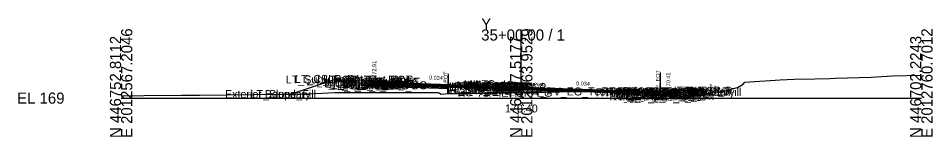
# Model space of a CAD drawing. Extents: x -26 to 3203, y -10 to 9532.
# Drawn here: x 1974.3 to 2202.8, y 8990.3 to 9020 of the extents above; entities that cross this region are included whole.
import ezdxf

# ---------------------------------------------------------------- set-up
doc = ezdxf.new("R2010")
doc.units = 0
for name, color, linetype in [('Default', 7, 'Continuous'), ('Exist CMT Pavement', 7, 'Continuous'), ('Exist Cross Section Cell', 7, 'Continuous'), ('Exist XS Center Line Elevation Label', 7, 'Continuous'), ('Exist XS Ground Line', 7, 'Continuous'), ('Prop CMT Conc Surface', 7, 'Continuous'), ('Prop CMT Concrete Structures', 7, 'Continuous'), ('Prop CMT Pvmt Course 1', 7, 'Continuous'), ('Prop CMT Pvmt Course 1 CG', 7, 'Continuous'), ('Prop CMT Pvmt Course 1 Wedge', 7, 'Continuous'), ('Prop CMT Pvmt Course 2', 7, 'Continuous'), ('Prop CMT Pvmt Course 2 Wedge', 7, 'Continuous'), ('Prop CMT Pvmt Course 3', 7, 'Continuous'), ('Prop CMT Pvmt Course 3 Wedge', 7, 'Continuous'), ('Prop CMT Pvmt Surface', 7, 'Continuous'), ('Prop CMT Pvmt Wedge Surface 1', 7, 'Continuous'), ('Prop CMT Pvmt Wedge Surface 2', 7, 'Continuous'), ('Prop CMT Pvmt Wedge Surface 3', 7, 'Continuous'), ('Prop CMT Slope Grass', 7, 'Continuous'), ('Prop CMT Subgrade Earthwork', 7, 'Continuous'), ('Prop XS Hydro Elevations', 7, 'Continuous'), ('Prop XS Label Text', 7, 'Continuous'), ('Prop XS SE Text', 7, 'Continuous'), ('Prop XS Side Slope Text', 7, 'Continuous'), ('Scratch_Level_0', 7, 'Continuous')]:
    doc.layers.add(name, color=color, linetype=linetype)

msp = doc.modelspace()

# ---------------------------------------------------------------- linework, layer by layer
at = {"layer": 'Exist CMT Pavement'}
for points in [[(2114.87, 9001.67), (2096, 9001.34)], [(2132.75, 9001.5), (2114.87, 9001.67)]]:
    msp.add_lwpolyline(points, dxfattribs=at)
at = {"layer": 'Exist Cross Section Cell'}
for p, q in [((2100, 9000), (2100, 9017.23)), ((2000, 9000), (2100, 9000)), ((2100, 9000), (2200, 9000))]:
    msp.add_line(p, q, dxfattribs=at)
at = {"layer": 'Exist XS Ground Line'}
msp.add_lwpolyline([(2000, 9000.58), (2005.69, 9000.63), (2015.07, 9000.72), (2019.58, 9000.75), (2040.24, 9001), (2041.62, 9001.01), (2045.25, 9001.08), (2046.89, 9001.09), (2053.45, 9001.4), (2054.76, 9001.42), (2063.44, 9001.43), (2077.33, 9001.4), (2079.21, 9001.42), (2079.58, 9001.21), (2080.02, 9000.95), (2080.98, 9001.05), (2081.74, 9001.12), (2082.58, 9001.15), (2083.46, 9001.17), (2085.1, 9001.2), (2086.1, 9001.21), (2087.68, 9001.23), (2090.25, 9001.27), (2092.14, 9001.3), (2092.44, 9001.3), (2092.82, 9001.31), (2093.83, 9001.32), (2095.4, 9001.34), (2096.31, 9001.35), (2097.98, 9001.37), (2098.36, 9001.38), (2100, 9001.4), (2100.55, 9001.41), (2101.04, 9001.41), (2103.12, 9001.44), (2103.97, 9001.47), (2105.72, 9001.52), (2106.54, 9001.54), (2108.3, 9001.58), (2109.59, 9001.6), (2110.85, 9001.62), (2111.97, 9001.64), (2113.43, 9001.66), (2113.97, 9001.66), (2116.11, 9001.69), (2118.85, 9001.7), (2119.53, 9001.7), (2120.93, 9001.7), (2121.28, 9001.7), (2121.87, 9001.69), (2124.12, 9001.65), (2125.6, 9001.63), (2126.45, 9001.61), (2127.07, 9001.6), (2129.13, 9001.57), (2129.48, 9001.56), (2131.61, 9001.52), (2132.36, 9001.51), (2134.18, 9001.47), (2134.76, 9001.46), (2135.84, 9001.45), (2136.75, 9001.43), (2139.37, 9001.39), (2141.38, 9001.35), (2141.9, 9001.34), (2142.76, 9001.33), (2144.45, 9001.29), (2144.87, 9001.28), (2145.3, 9001.26), (2145.88, 9001.22), (2147.07, 9001.12), (2147.85, 9001.59), (2149.84, 9001.61), (2150.21, 9001.62), (2150.85, 9001.79), (2154.09, 9002.65), (2155.46, 9003.51), (2155.92, 9003.98), (2164.74, 9004.55), (2168.18, 9004.74), (2173.38, 9004.86), (2177.15, 9004.96), (2178.49, 9004.99), (2187.49, 9005.26), (2192.76, 9005.59), (2200, 9005.74)], dxfattribs=at)
at = {"layer": 'Prop CMT Conc Surface'}
for points in [[(2058.75, 9004.5), (2053.75, 9004.6)], [(2063.25, 9003.91), (2063.25, 9004.41), (2062.75, 9004.41)], [(2065.25, 9003.93), (2063.25, 9003.91)], [(2136.75, 9001.41), (2136.75, 9001.91), (2137.25, 9001.91)], [(2141.25, 9002), (2146.25, 9002.1)], [(2134.75, 9001.55), (2136.75, 9001.41)]]:
    msp.add_lwpolyline(points, dxfattribs=at)
at = {"layer": 'Prop CMT Concrete Structures'}
for points in [[(2053.75, 9004.27), (2053.75, 9004.6)], [(2053.75, 9004.6), (2058.75, 9004.5)], [(2058.75, 9004.17), (2053.75, 9004.27)], [(2058.75, 9004.5), (2058.75, 9004.17)], [(2065.25, 9003.93), (2063.25, 9003.91), (2063.25, 9004.41), (2062.75, 9004.41)], [(2062.75, 9004.41), (2062.75, 9003.43), (2065.25, 9003.34)], [(2065.25, 9003.34), (2065.25, 9003.93)], [(2096, 9002.88), (2095.99, 9003.04), (2095.24, 9003.29), (2094, 9003.45), (2092.76, 9003.43), (2092.01, 9003.18), (2092, 9003.01)], [(2092, 9003.01), (2096, 9002.88)], [(2134.75, 9001.55), (2136.75, 9001.41), (2136.75, 9001.91), (2137.25, 9001.91)], [(2137.25, 9001.91), (2137.25, 9000.89), (2134.75, 9000.97)], [(2146.25, 9002.1), (2141.25, 9002)], [(2141.25, 9002), (2141.25, 9001.66)], [(2146.25, 9001.76), (2146.25, 9002.1)], [(2134.75, 9000.97), (2134.75, 9001.55)], [(2141.25, 9001.66), (2146.25, 9001.76)]]:
    msp.add_lwpolyline(points, dxfattribs=at)
at = {"layer": 'Prop CMT Pvmt Course 1'}
for points in [[(2092, 9003.01), (2065.25, 9003.93)], [(2065.25, 9003.93), (2065.25, 9003.68)], [(2065.25, 9003.68), (2092, 9002.76)], [(2092, 9003.01), (2096, 9002.88)], [(2092, 9002.76), (2092, 9003.01)], [(2092, 9002.76), (2092, 9003.01)], [(2096, 9002.63), (2092, 9002.76)], [(2096, 9002.88), (2134.75, 9001.55)], [(2096, 9002.63), (2096, 9002.88)], [(2096, 9002.88), (2096, 9002.63)], [(2132.75, 9001.5), (2096, 9002.75)], [(2096, 9002.75), (2096, 9002.63), (2096, 9002.63)], [(2132.75, 9001.37), (2132.75, 9001.5)], [(2134.75, 9001.3), (2133.75, 9001.34)], [(2134.75, 9001.55), (2134.75, 9001.3)]]:
    msp.add_lwpolyline(points, dxfattribs=at)
msp.add_lwpolyline([(2092, 9002.76), (2092, 9002.89), (2092, 9002.89), (2092, 9002.76)], close=True, dxfattribs=at)
at = {"layer": 'Prop CMT Pvmt Course 1 CG'}
for points in [[(2065.25, 9003.34), (2062.25, 9003.45), (2061.93, 9003.12)], [(2061.93, 9003.12), (2065.25, 9003.01)], [(2065.25, 9003.01), (2065.25, 9003.34)], [(2134.75, 9000.97), (2137.75, 9000.87), (2138.1, 9000.52)], [(2134.75, 9000.64), (2134.75, 9000.97)], [(2138.1, 9000.52), (2134.75, 9000.64)]]:
    msp.add_lwpolyline(points, dxfattribs=at)
at = {"layer": 'Prop CMT Pvmt Course 1 Wedge'}
for points in [[(2096, 9002.75), (2096.31, 9002.74), (2097.98, 9002.68), (2098.36, 9002.67), (2099.77, 9002.62), (2100.39, 9002.6), (2100.55, 9002.6), (2101.04, 9002.58), (2103.08, 9002.51), (2103.12, 9002.51), (2103.97, 9002.48), (2105.72, 9002.42), (2106.54, 9002.39), (2108.3, 9002.33), (2109.59, 9002.29), (2110.85, 9002.25), (2111.97, 9002.21), (2113.43, 9002.16), (2113.43, 9002.16), (2113.97, 9002.14), (2116.11, 9002.07), (2118.4, 9001.99), (2118.68, 9001.98), (2118.85, 9001.97), (2119.53, 9001.95), (2120.93, 9001.9), (2121.28, 9001.89), (2121.87, 9001.87), (2123.86, 9001.8), (2123.92, 9001.8), (2124.12, 9001.79), (2125.6, 9001.74), (2126.45, 9001.71), (2127.07, 9001.69), (2129.04, 9001.62), (2129.13, 9001.62), (2129.48, 9001.61), (2131.61, 9001.54), (2132.36, 9001.51), (2132.66, 9001.5)], [(2096, 9002.63), (2096, 9002.75)], [(2132.66, 9001.5), (2132.36, 9001.51), (2131.61, 9001.52), (2129.48, 9001.56), (2129.13, 9001.57), (2129.04, 9001.57), (2127.07, 9001.6), (2126.45, 9001.61), (2125.6, 9001.63), (2125.03, 9001.64), (2124.12, 9001.67), (2123.92, 9001.67), (2123.86, 9001.68), (2121.87, 9001.74), (2121.28, 9001.76), (2120.93, 9001.78), (2119.53, 9001.82), (2118.85, 9001.85), (2118.68, 9001.85), (2118.4, 9001.86), (2116.11, 9001.94), (2113.97, 9002.01), (2113.43, 9002.03), (2113.43, 9002.03), (2111.97, 9002.08), (2110.85, 9002.12), (2109.59, 9002.16), (2108.3, 9002.21), (2106.54, 9002.27), (2105.72, 9002.3), (2103.97, 9002.35), (2103.12, 9002.38), (2103.08, 9002.39), (2101.04, 9002.46), (2100.55, 9002.47), (2100.39, 9002.48), (2099.77, 9002.5), (2098.36, 9002.55), (2097.98, 9002.56), (2096.31, 9002.62), (2096, 9002.63)]]:
    msp.add_lwpolyline(points, dxfattribs=at)
at = {"layer": 'Prop CMT Pvmt Course 2'}
for points in [[(2092, 9002.76), (2065.25, 9003.68)], [(2065.25, 9003.68), (2065.25, 9003.34)], [(2065.25, 9003.34), (2092, 9002.43)], [(2092, 9002.76), (2096, 9002.63)], [(2092, 9002.43), (2092, 9002.76)], [(2092, 9002.43), (2092, 9002.76)], [(2096, 9002.29), (2092, 9002.43)], [(2096, 9002.63), (2096, 9002.29)], [(2132.75, 9001.04), (2132.75, 9001.37)], [(2132.75, 9001.37), (2134.75, 9001.3)], [(2134.75, 9000.97), (2132.75, 9001.04)], [(2134.75, 9001.3), (2134.75, 9000.97)]]:
    msp.add_lwpolyline(points, dxfattribs=at)
at = {"layer": 'Prop CMT Pvmt Course 2 Wedge'}
for points in [[(2096, 9002.63), (2096.31, 9002.62), (2097.98, 9002.56), (2098.36, 9002.55), (2099.77, 9002.5), (2100.39, 9002.48), (2100.55, 9002.47), (2101.04, 9002.46), (2103.08, 9002.39), (2103.12, 9002.38), (2103.97, 9002.35), (2105.72, 9002.3), (2106.54, 9002.27), (2108.3, 9002.21), (2109.59, 9002.16), (2110.85, 9002.12), (2111.97, 9002.08), (2113.43, 9002.03), (2113.43, 9002.03), (2113.97, 9002.01), (2116.11, 9001.94), (2118.4, 9001.86), (2118.68, 9001.85), (2118.85, 9001.85), (2119.53, 9001.82), (2120.93, 9001.78), (2121.28, 9001.76), (2121.87, 9001.74), (2123.86, 9001.68), (2123.92, 9001.67), (2124.12, 9001.67), (2125.03, 9001.64)], [(2096, 9002.29), (2096, 9002.63)], [(2125.03, 9001.64), (2124.12, 9001.65), (2123.92, 9001.65), (2123.86, 9001.66), (2121.87, 9001.69), (2121.28, 9001.7), (2120.93, 9001.7), (2119.53, 9001.7), (2118.85, 9001.7), (2118.68, 9001.7), (2118.4, 9001.7), (2116.11, 9001.69), (2114.34, 9001.67), (2113.97, 9001.68), (2113.43, 9001.7), (2113.43, 9001.7), (2111.97, 9001.75), (2110.85, 9001.79), (2109.59, 9001.83), (2108.3, 9001.87), (2106.54, 9001.93), (2105.72, 9001.96), (2103.97, 9002.02), (2103.12, 9002.05), (2103.08, 9002.05), (2101.04, 9002.12), (2100.55, 9002.14), (2100.39, 9002.14), (2099.77, 9002.16), (2098.36, 9002.21), (2097.98, 9002.23), (2096.31, 9002.28), (2096, 9002.29)]]:
    msp.add_lwpolyline(points, dxfattribs=at)
at = {"layer": 'Prop CMT Pvmt Course 3'}
for points in [[(2092, 9002.43), (2065.25, 9003.34)], [(2065.25, 9003.34), (2065.25, 9003.01)], [(2065.25, 9003.01), (2081.74, 9002.45)], [(2092, 9002.43), (2096, 9002.29)], [(2132.75, 9001.04), (2134.75, 9000.97)], [(2132.75, 9000.71), (2132.75, 9001.04)], [(2134.75, 9000.64), (2132.75, 9000.71)], [(2134.75, 9000.97), (2134.75, 9000.64)]]:
    msp.add_lwpolyline(points, dxfattribs=at)
at = {"layer": 'Prop CMT Pvmt Course 3 Wedge'}
for points in [[(2096, 9002.29), (2096.31, 9002.28), (2097.98, 9002.23), (2098.36, 9002.21), (2099.77, 9002.16), (2100.39, 9002.14), (2100.55, 9002.14), (2101.04, 9002.12), (2103.08, 9002.05), (2103.12, 9002.05), (2103.97, 9002.02), (2105.72, 9001.96), (2106.54, 9001.93), (2108.3, 9001.87), (2109.59, 9001.83), (2110.85, 9001.79), (2111.97, 9001.75), (2113.43, 9001.7), (2113.43, 9001.7), (2113.97, 9001.68), (2114.34, 9001.67)], [(2114.34, 9001.67), (2113.97, 9001.66), (2113.43, 9001.66), (2113.43, 9001.66), (2111.97, 9001.64), (2110.85, 9001.62), (2109.59, 9001.6), (2108.3, 9001.58), (2106.54, 9001.54), (2105.72, 9001.52), (2103.97, 9001.47), (2103.12, 9001.44), (2103.08, 9001.44), (2101.04, 9001.41), (2100.55, 9001.41), (2100.39, 9001.4), (2099.77, 9001.4), (2098.36, 9001.38), (2097.98, 9001.37), (2096.31, 9001.35), (2096, 9001.34)]]:
    msp.add_lwpolyline(points, dxfattribs=at)
at = {"layer": 'Prop CMT Pvmt Surface'}
for points in [[(2092, 9003.01), (2065.25, 9003.93)], [(2092, 9003.01), (2096, 9002.88)], [(2096, 9002.88), (2134.75, 9001.55)]]:
    msp.add_lwpolyline(points, dxfattribs=at)
at = {"layer": 'Prop CMT Pvmt Wedge Surface 1'}
for points in [[(2096, 9002.88), (2096, 9002.63), (2096, 9002.63), (2096, 9002.75)], [(2096, 9002.75), (2132.75, 9001.5)], [(2132.75, 9001.5), (2132.75, 9001.37)], [(2134.75, 9001.3), (2134.75, 9001.55)]]:
    msp.add_lwpolyline(points, dxfattribs=at)
at = {"layer": 'Prop CMT Pvmt Wedge Surface 2'}
for points in [[(2096, 9002.88), (2096, 9002.63)], [(2096, 9002.63), (2132.75, 9001.37)], [(2134.75, 9001.3), (2134.75, 9001.55)]]:
    msp.add_lwpolyline(points, dxfattribs=at)
at = {"layer": 'Prop CMT Pvmt Wedge Surface 3'}
for points in [[(2096, 9002.88), (2096, 9002.29)], [(2096, 9002.29), (2132.75, 9001.04)], [(2134.75, 9000.97), (2134.75, 9001.55)]]:
    msp.add_lwpolyline(points, dxfattribs=at)
at = {"layer": 'Prop CMT Slope Grass'}
for points in [[(2062.75, 9004.41), (2053.25, 9004.6), (2042.52, 9001.03)], [(2137.25, 9001.91), (2146.25, 9002.09)], [(2146.25, 9002.09), (2146.75, 9002.1), (2148.27, 9001.59)]]:
    msp.add_lwpolyline(points, dxfattribs=at)
at = {"layer": 'Prop CMT Subgrade Earthwork'}
for p, q in [((2081.74, 9002.45), (2081.74, 9001.12)), ((2132.75, 9001.5), (2132.75, 9000.71))]:
    msp.add_line(p, q, dxfattribs=at)
for points in [[(2065.25, 9003.01), (2061.93, 9003.12), (2060.59, 9004.46)], [(2081.74, 9002.45), (2065.25, 9003.01)], [(2134.75, 9000.64), (2138.1, 9000.52), (2139.52, 9001.95)], [(2132.75, 9000.71), (2134.75, 9000.64)]]:
    msp.add_lwpolyline(points, dxfattribs=at)
at = {"layer": 'Prop XS Label Text'}
for p, q in [((2081.74, 9006.12), (2081.74, 9001.12)), ((2134.76, 9006.46), (2134.76, 9001.46))]:
    msp.add_line(p, q, dxfattribs=at)

# ---------------------------------------------------------------- texts
at = {"layer": 'Default'}
msp.add_text('-', height=0.0001, dxfattribs=at).set_placement((2000, 9000))
at = {"layer": 'Exist Cross Section Cell'}
for s, p in [('Y', (2090, 9017.23)), ('35+00.00 / 1', (2090, 9014.43)), ('EL 169', (1974, 8998.6))]:
    msp.add_text(s, height=2.8, dxfattribs=at).set_placement(p)
for s, p in [('E 2012567.2046', (2002.8, 8990)), ('E 2012663.9529', (2102.8, 8990)), ('E 2012760.7012', (2202.8, 8990)), ('N 446752.8112', (2000, 8990)), ('N 446727.5177', (2100, 8990)), ('N 446702.2243', (2200, 8990))]:
    msp.add_text(s, height=2.8, rotation=90, dxfattribs=at).set_placement(p)
at = {"layer": 'Exist XS Center Line Elevation Label'}
msp.add_text('170.40', height=2, dxfattribs=at).set_placement((2095.95, 8996.4))
at = {"layer": 'Prop XS Hydro Elevations'}
for s, p in [('172.91', (2063.75, 9005.13)), ('170.41', (2137.25, 9002.19))]:
    msp.add_text(s, height=1, rotation=90, dxfattribs=at).set_placement(p)
at = {"layer": 'Prop XS Label Text'}
for p in [(2081.64, 9002.15), (2134.66, 9002.49)]:
    msp.add_text('E. EOT', height=1, rotation=90, dxfattribs=at).set_placement(p)
at = {"layer": 'Prop XS SE Text'}
for p in [(2076.94, 9004.66), (2113.69, 9003.19)]:
    msp.add_text('0.034', height=1, rotation=357.7094, dxfattribs=at).set_placement(p)
at = {"layer": 'Prop XS Side Slope Text'}
for rotation, p in [(18.4349, (2046.55, 9003.38)), (341.5651, (2146.75, 9002.67))]:
    msp.add_text('3:1', height=1, rotation=rotation, dxfattribs=at).set_placement(p)
at = {"layer": 'Scratch_Level_0'}
for s, p in [('LT_Sub_Trench_Out_DLT', (2041.17, 9003.67)), ('LT_CSLP_Pnt', (2043.42, 9003.82)), ('LT_CG1_Shelf_Out', (2048.8, 9002.67)), ('LT_CG_Top_Face', (2050.51, 9003.63)), ('LT_CG_Top_BOC', (2051.03, 9003.63)), ('LT_CG_Bot_BOC', (2051.06, 9002.65)), ('LT_CG_Top_Gut', (2051.49, 9003.13)), ('LT_Sub_OEOP', (2052.04, 9002.35)), ('LT_Sub_OEOT_CG', (2052.62, 9002.21)), ('LT_CG_Bot_IE', (2055.16, 9002.55)), ('LT_Sub_OEOT', (2055.33, 9002.21)), ('LT_PV2_OEOT', (2055.42, 9002.88)), ('LT_PV3_OEOT', (2055.42, 9002.55)), ('LT_PV1_OEOT', (2055.99, 9003.13)), ('MI_Face In', (2083.9, 9002.23)), ('MI_Top In', (2085.61, 9002.48)), ('MI_Top Out', (2086.47, 9002.32)), ('MI_Crown', (2087.07, 9002.5)), ('Exterior Boundary', (2025.97, 9000.01)), ('LT_Slope_Fill', (2032.35, 9000.01)), ('LT_Sub_OEEOP', (2081.21, 9001.14)), ('LT_PV2_OEEOP', (2081.31, 9001.81)), ('LT_PV3_OEEOP', (2081.31, 9001.48)), ('LT_PV1_OEEOP', (2081.87, 9001.94)), ('LT_PV2_IEEOP', (2081.95, 9001.81)), ('LT_PV1_IEEOP', (2082.52, 9001.94)), ('LT_PV2_PGL1', (2082.88, 9001.81)), ('LT_PV3_PGL1', (2082.88, 9001.48)), ('LT_PV2_PGL', (2083.21, 9001.81)), ('LT_PV4_PGL', (2083.21, 9001.14)), ('LT_PV1_PGL', (2083.78, 9002.06)), ('RT_PV_IEEOP_EG', (2084.14, 9000.34)), ('RT_PV2_IEEOP', (2085.91, 9001.65)), ('RT_PV3_IEEOP', (2085.91, 9001.32)), ('MI_Face Out', (2086.26, 9002.07)), ('RT_PV1_IEEOP', (2086.47, 9001.78)), ('RT_PV2_PGL1', (2086.83, 9001.65)), ('RT_PV3_PGL1', (2086.83, 9001.32)), ('RT_PV2_PGL', (2087.17, 9001.65)), ('RT_PV3_PGL', (2087.17, 9001.32)), ('RT_PV4_PGL', (2087.17, 9000.98)), ('MI_Bot Out', (2087.26, 9001.9)), ('RT_PV1_PGL', (2087.73, 9001.9)), ('RT_PV_EG_TestPt', (2101.24, 9000.67)), ('RT_PV_Sub_Tie_Out', (2118.63, 9000.48)), ('RT_Sub_Trench_Out_DLT', (2120.05, 9000.74)), ('RT_PV_OEEOP_EG', (2121.25, 9000.48)), ('RT_PV2_OEEOP', (2123.01, 9000.14)), ('RT_PV1_OEEOP', (2123.58, 9000.27)), ('RT_CG_Top_Face', (2123.96, 9000.69)), ('RT_PV2_OEOT', (2124.88, 9000.1)), ('RT_CG_Top_Gut', (2124.94, 9000.19)), ('RT_PV1_OEOT', (2125.44, 9000.35)), ('RT_CG_Top_BOC', (2125.49, 9000.69)), ('Exterior Boundary', (2131.92, 9000.54)), ('RT_Slope_Fill', (2138.25, 9000.54)), ('RT_Shld_O', (2138.79, 9000.87)), ('CSLP_Pnt', (2139.62, 9000.88)), ('RT_Sub_OEOT_CG', (2122.07, 8999.43)), ('RT_Sub_OEEOP', (2122.92, 8999.47)), ('RT_PV3_OEEOP', (2123.01, 8999.81)), ('RT_CG1_Shelf_Out', (2124.25, 8999.65)), ('RT_CG_Bot_IE', (2124.62, 8999.77)), ('RT_Sub_OEOT', (2124.78, 8999.43)), ('RT_PV3_OEOT', (2124.88, 8999.77)), ('RT_CG_Bot_BOC', (2125.52, 8999.67)), ('RT_Sub_OEOP', (2128.16, 8999.3))]:
    msp.add_text(s, height=2, dxfattribs=at).set_placement(p)

doc.saveas('drawing.dxf')
